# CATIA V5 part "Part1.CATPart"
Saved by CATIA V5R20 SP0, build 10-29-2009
Part number: Part1
Bounding box of the stored display mesh (mm): x 0 to 60, y -300 to 300, z -20 to 20
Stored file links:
  E:\Ehsan\Catia\Tamrin\Digital Mockup\3\Part1.CATPart
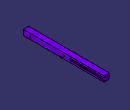
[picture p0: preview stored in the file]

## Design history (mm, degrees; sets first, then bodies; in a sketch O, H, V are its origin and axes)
Body1 (main body)
  Sketch1 on yz-plane, origin (0, 0, 0), H (0, 1, 0), V (0, 0, 1)
    line L1 (300, 20) -> (300, -20)
    line L2 (300, -20) -> (-300, -20)
    line L3 (-300, -20) -> (-300, 20)
    line L4 (-300, 20) -> (300, 20)
    distance L2 L4 = 40
    distance L1 L3 = 600
    vertical: L1 V, L3 V
    horizontal: L2 H, L4 H
    equidistance: L1 L3 O, L2 L4 O
  Pad1: profile Sketch1, direction (1, 0, 0), length 40
  Sketch2 on end face of Pad1, origin (40, 0, 0), H (0, 1, 0), V (0, 0, 1)
    circle A1 centre (0, 0) radius 6
    circle A2 centre (-250, 0) radius 6
    radius A1 = 6
  Pad2: profile Sketch2, direction (1, 0, 0), length 20
  Sketch3 on face of Pad1 from Sketch1.L1, origin (0, 300, 0), H (-1, 0, 0), V (0, 0, 1)
    line L1 (-40, -7.5) -> (-40, 7.5)
    point P1 (-40, -7.5)
    line L2 (-40, -7.5) -> (-28, -12.5)
    point P2 (-28, -12.5)
    line L3 (-28, -12.5) -> (-28, 12.5)
    line L4 (-28, 12.5) -> (-40, 7.5)
    point P4 (-40, 7.5)
    distance P1 H = 7.5
    distance P2 H = 12.5
    distance P2 V = 28
    length L3 = 25
    distance P4 H = 7.5
    vertical: L3 V
  Pocket1: profile Sketch3, direction (0, -1, 0), length 250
